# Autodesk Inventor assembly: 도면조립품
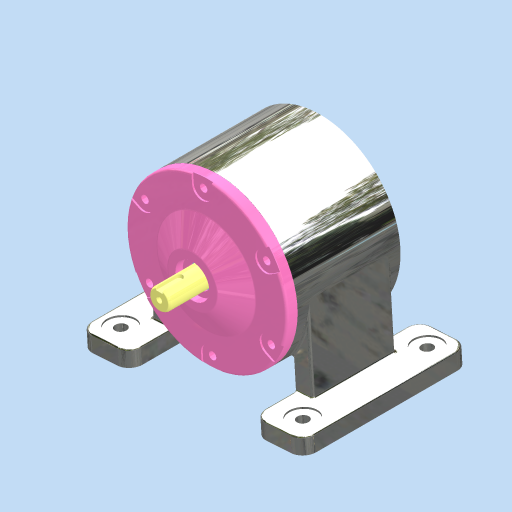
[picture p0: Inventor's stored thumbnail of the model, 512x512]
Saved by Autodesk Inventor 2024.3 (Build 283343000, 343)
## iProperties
Created: 2025-12
Part Number: 도면조립품
Document SubType Name: Assembly
Designer: PC2-03
Author: PC2-03
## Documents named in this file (12)
- C:\Users\PC2-03\Desktop\751203V1018\도면조립품.iam
- C:\Users\PC2-03\Desktop\751203V1018\본체.ipt
- C:\Users\PC2-03\Desktop\751203V1018\출력 축\출력 축\출력 축.ipt
- C:\Users\PC2-03\Desktop\751203V1018\기어 축\기어 축\기어 축.ipt
- C:\Users\PC2-03\Desktop\751203V1018\엔드 캡\엔드 캡\엔드 캡.ipt
- C:\Users\PC2-03\Desktop\751203V1018\칼라 1\칼라 1\칼라 1.ipt
- C:\Users\PC2-03\Desktop\751203V1018\종동 기어\종동 기어\종동 기어.ipt
- C:\Users\PC2-03\Desktop\751203V1018\깊은 홈 볼 베어링 6004\깊은 홈 볼 베어링 6004\깊은 홈 볼 베어링 6004.ipt
- C:\Users\PC2-03\Desktop\751203V1018\평행 키 6x6x16\평행 키 6x6x16\평행 키 6x6x16.ipt
- C:\Users\PC2-03\Desktop\751203V1018\깊은 홈 볼 베어링 6005\깊은 홈 볼 베어링 6005\깊은 홈 볼 베어링 6005.ipt
- C:\Users\PC2-03\Desktop\751203V1018\커버\커버\커버.ipt
- C:\Users\PC2-03\Desktop\751203V1018\구동 기어\구동 기어\구동 기어.ipt
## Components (1 placed, 1 different names)
1. 구동 기어:1
